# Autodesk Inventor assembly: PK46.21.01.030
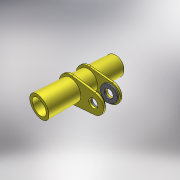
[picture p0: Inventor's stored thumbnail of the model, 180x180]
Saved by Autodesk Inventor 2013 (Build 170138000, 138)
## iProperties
Created: 2005-04
Part Number: PK46.21.01.030
Document SubType Name: Assembly
Designer: salex
Manufacturer: Standard
Standards Organization: Custom
Author: salex
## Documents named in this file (4)
- C:\Product Design Suite 2013 Test Drive\Dynamic Simulation\Workspace\Assy, Chassis, Front\PK46.21.01.030.iam
- C:\Product Design Suite 2013 Test Drive\Dynamic Simulation\Workspace\Assy, Chassis, Front\PK46.21.01.006.ipt
- C:\Product Design Suite 2013 Test Drive\Dynamic Simulation\Workspace\Assy, Chassis, Front\PK46.21.01.007.ipt
- C:\Product Design Suite 2013 Test Drive\Dynamic Simulation\Workspace\Assy, Chassis, Front\PK46.25.02.003.ipt
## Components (5 placed, 3 different names)
1. PK46.21.01.006:1 — Вставка:1, Совмещение:1
2. PK46.21.01.007:1 — Вставка:1, Вставка:2, Вставка:3
3. PK46.21.01.007:2 — Вставка:2, Совмещение:1, Вставка:4
4. PK46.25.02.003:1 — Вставка:3
5. PK46.25.02.003:2 — Вставка:4, Совмещение:2
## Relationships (6: Insert 4, Mate 2)
- Вставка:1 [Insert]: PK46.21.01.006:1 ↔ PK46.21.01.007:1
- Вставка:2 [Insert]: PK46.21.01.007:1 ↔ PK46.21.01.007:2
- Совмещение:1 [Mate]: PK46.21.01.006:1 ↔ PK46.21.01.007:2
- Вставка:3 [Insert]: PK46.21.01.007:1 ↔ PK46.25.02.003:1
- Вставка:4 [Insert]: PK46.21.01.007:2 ↔ PK46.25.02.003:2
- Совмещение:2 [Mate]: PK46.25.02.003:2
